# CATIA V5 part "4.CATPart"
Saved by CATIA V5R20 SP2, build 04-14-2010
Part number: 4
Bounding box of the stored display mesh (mm): x -150 to -92.388, y -57.403 to 57.403, z -50 to 50
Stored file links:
  C:\Users\Orange\Desktop\Assembly Design-7\4.CATPart
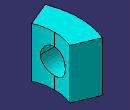
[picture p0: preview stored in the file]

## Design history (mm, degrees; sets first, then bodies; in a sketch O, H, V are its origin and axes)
Body1 (main body)
  Sketch1 on xy-plane, origin (0, 0, 0), H (1, 0, 0), V (0, 1, 0)
    circle A1 centre (0, 0) radius 150
    circle A2 centre (0, 0) radius 100
  Pad1: profile Sketch1, direction (0, 0, 1), length 50, mirrored extent
  Sketch2 on xy-plane, origin (0, 0, 0), H (1, 0, 0), V (0, 1, 0)
    point P2 (0, 0)
    line L1 (0, 0) -> (-248.3258, 102.8599)
    point P4 (0, 0)
    line L2 (0, 0) -> (-248.3258, -102.8599)
    line L3 (-248.3258, 102.8599) -> (144.4644, 265.559)
    line L4 (144.4644, 265.559) -> (265.4909, -94.007)
    line L5 (265.4909, -94.007) -> (-96.3089, -264.1413)
    line L6 (-96.3089, -264.1413) -> (-248.3258, -102.8599)
    coincidence: P2 P4
  Pocket1: profile Sketch2, direction (0, 0, -1), length 100, mirrored extent
  Sketch3 on yz-plane, origin (0, 0, 0), H (0, 1, 0), V (0, 0, 1)
    circle A1 centre (0, 0) radius 25
  Pocket2: profile Sketch3, direction (-1, 0, 0), length 1100
  Sketch4 on zx-plane, origin (0, 0, 0), H (-1, 0, 0), V (0, 0, 1)
    intersected line E1 through (0, 0) direction (-1, 0) from axis of face of Pocket2 from Sketch3.A1
  Sketch5 on zx-plane, origin (0, 0, 0), H (-1, 0, 0), V (0, 0, 1)
    intersected line E1 through (0, 0) direction (-1, 0) from axis of face of Pocket2 from Sketch3.A1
